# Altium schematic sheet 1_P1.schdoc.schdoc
size 431 x 309 mm; Symbol: Sheet-Symbol_A4; Device: Sheet-Symbol_A4; @Page Name: P1; @Create Date: 2023-10-07; @Page Count: 1; @Page No: 1; @Project Name: circuller; @Schematic Name: Schematic1; @Update Date: 2023-10-11; Company: MPAM Lab; Page Size: A3; Version: 0.1
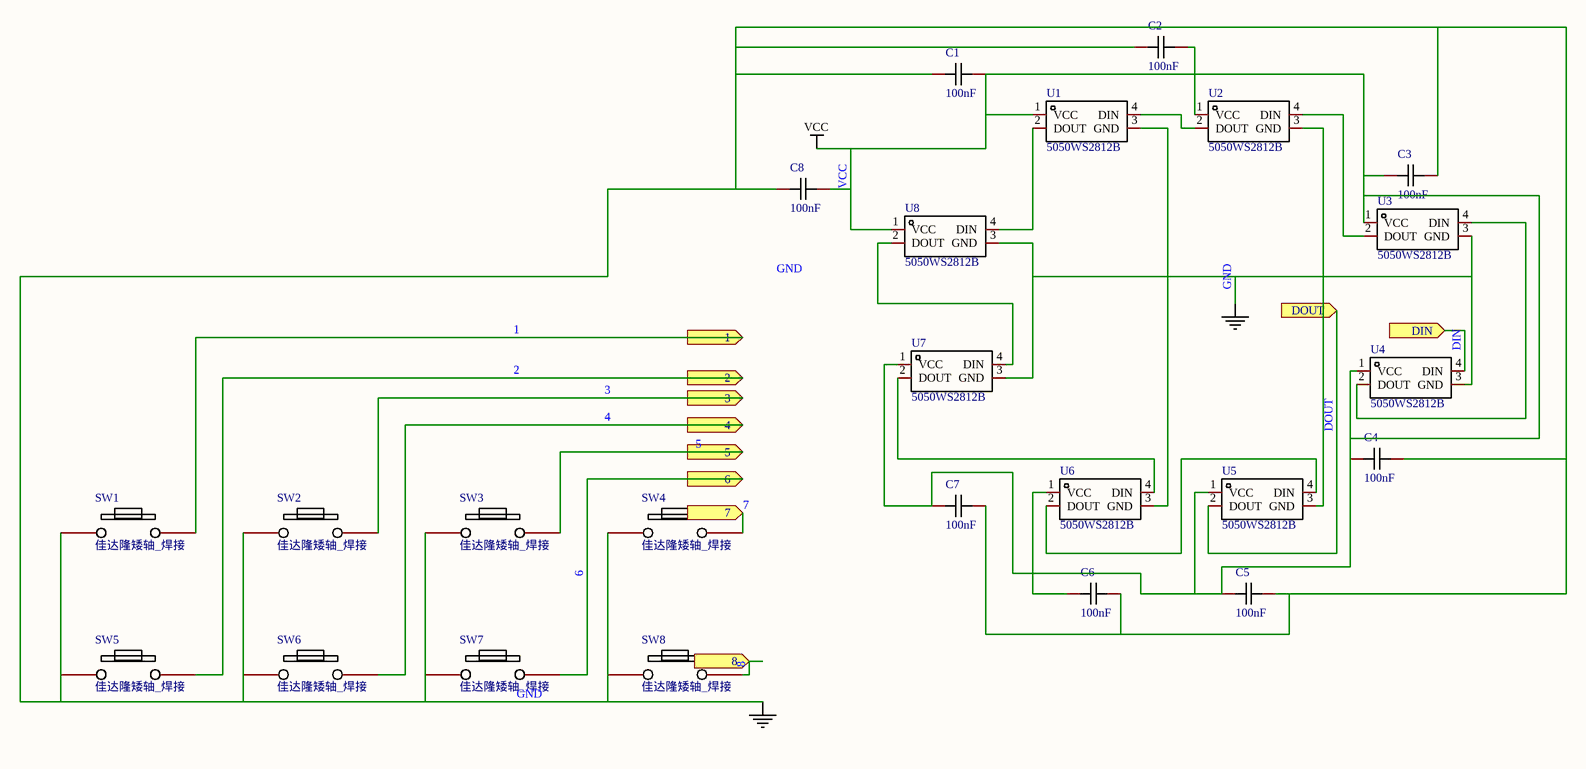
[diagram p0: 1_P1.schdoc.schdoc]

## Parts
C1  100nF  [C0603]
C2  100nF  [C0603]
C3  100nF  [C0603]
C4  100nF  [C0603]
C5  100nF  [C0603]
C6  100nF  [C0603]
C7  100nF  [C0603]
C8  100nF  [C0603]
SW1  佳达隆矮轴_焊接  [佳达隆矮轴焊接]
SW2  佳达隆矮轴_焊接  [佳达隆矮轴焊接]
SW3  佳达隆矮轴_焊接  [佳达隆矮轴焊接]
SW4  佳达隆矮轴_焊接  [佳达隆矮轴焊接]
SW5  佳达隆矮轴_焊接  [佳达隆矮轴焊接]
SW6  佳达隆矮轴_焊接  [佳达隆矮轴焊接]
SW7  佳达隆矮轴_焊接  [佳达隆矮轴焊接]
SW8  佳达隆矮轴_焊接  [佳达隆矮轴焊接]
U1  5050WS2812B  [LED-SMD_5050WS2812B]
U2  5050WS2812B  [LED-SMD_5050WS2812B]
U3  5050WS2812B  [LED-SMD_5050WS2812B]
U4  5050WS2812B  [LED-SMD_5050WS2812B]
U5  5050WS2812B  [LED-SMD_5050WS2812B]
U6  5050WS2812B  [LED-SMD_5050WS2812B]
U7  5050WS2812B  [LED-SMD_5050WS2812B]
U8  5050WS2812B  [LED-SMD_5050WS2812B]

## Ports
1 (in), 2 (in), 3 (in), 4 (in), 5 (in), 6 (in), 7 (in), 8 (in), DIN (in), DOUT (in)

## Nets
GND: C1.1 C2.1 C3.2 C4.2 C5.2 C6.2 C7.2 C8.1 SW1.1 SW2.1 SW3.1 SW4.1 SW5.1 SW6.1 SW7.1 SW8.1 U1.3(GND) U2.3(GND) U3.3(GND) U4.3(GND) U5.3(GND) U6.3(GND) U7.3(GND) U8.3(GND)
VCC: C1.2 C2.2 C3.1 C4.1 C5.1 C6.1 C7.1 C8.2 U1.1(VCC) U2.1(VCC) U3.1(VCC) U4.1(VCC) U5.1(VCC) U6.1(VCC) U7.1(VCC) U8.1(VCC)
1: SW1.2 ; port 1
2: SW5.2 ; port 2
3: SW2.2 ; port 3
4: SW6.2 ; port 4
5: SW3.2 ; port 5
6: SW7.2 ; port 6
7: SW4.2 ; port 7
8: SW8.2 ; port 8
DIN: U4.4(DIN) ; port DIN
DOUT: U5.2(DOUT) ; port DOUT
NetU1_2: U1.2(DOUT) U8.4(DIN)
NetU1_4: U1.4(DIN) U2.2(DOUT)
NetU2_4: U2.4(DIN) U3.2(DOUT)
NetU3_4: U3.4(DIN) U4.2(DOUT)
NetU5_4: U5.4(DIN) U6.2(DOUT)
NetU6_4: U6.4(DIN) U7.2(DOUT)
NetU7_4: U7.4(DIN) U8.2(DOUT)

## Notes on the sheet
- Labels drawn without touching a wire or pin: GND

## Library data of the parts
C1-C8 = CAP_0603: Symbol: CapAcitance; Convert to PCB: yes
SW1-SW8 = 佳达隆矮轴_焊接: Add into BOM: yes
U1-U8 = 5050WS2812B: Add into BOM: yes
